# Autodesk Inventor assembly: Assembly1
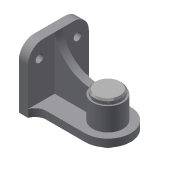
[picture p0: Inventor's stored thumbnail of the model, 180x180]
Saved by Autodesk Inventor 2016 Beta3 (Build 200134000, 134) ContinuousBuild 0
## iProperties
Created: 2016-03
Part Number: Assembly1
Document SubType Name: Assembly
Designer: Gaurav
Author: Gaurav
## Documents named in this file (3)
- D:\My Data\Books_Final Books\Autodesk Inventor 2015_resources\Chapter 7\Assembly1.iam
- D:\My Data\Books_Final Books\Autodesk Inventor 2015_resources\Chapter 6\Practical_4.ipt
- C:\Users\Gaurav\Documents\Inventor\Content Center Files\R2016\en-US\IS 6863  A\IS 6863 - A 24 x 55.ipt
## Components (2 placed, 2 different names)
1. Practical_4:1 — Mate:2
2. IS 6863 A A 24 x 55:1 — Mate:2
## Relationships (1: Mate 1)
- Mate:2: Practical_4:1 ↔ IS 6863 A A 24 x 55:1
